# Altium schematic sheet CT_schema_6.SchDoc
size 379 x 245 mm
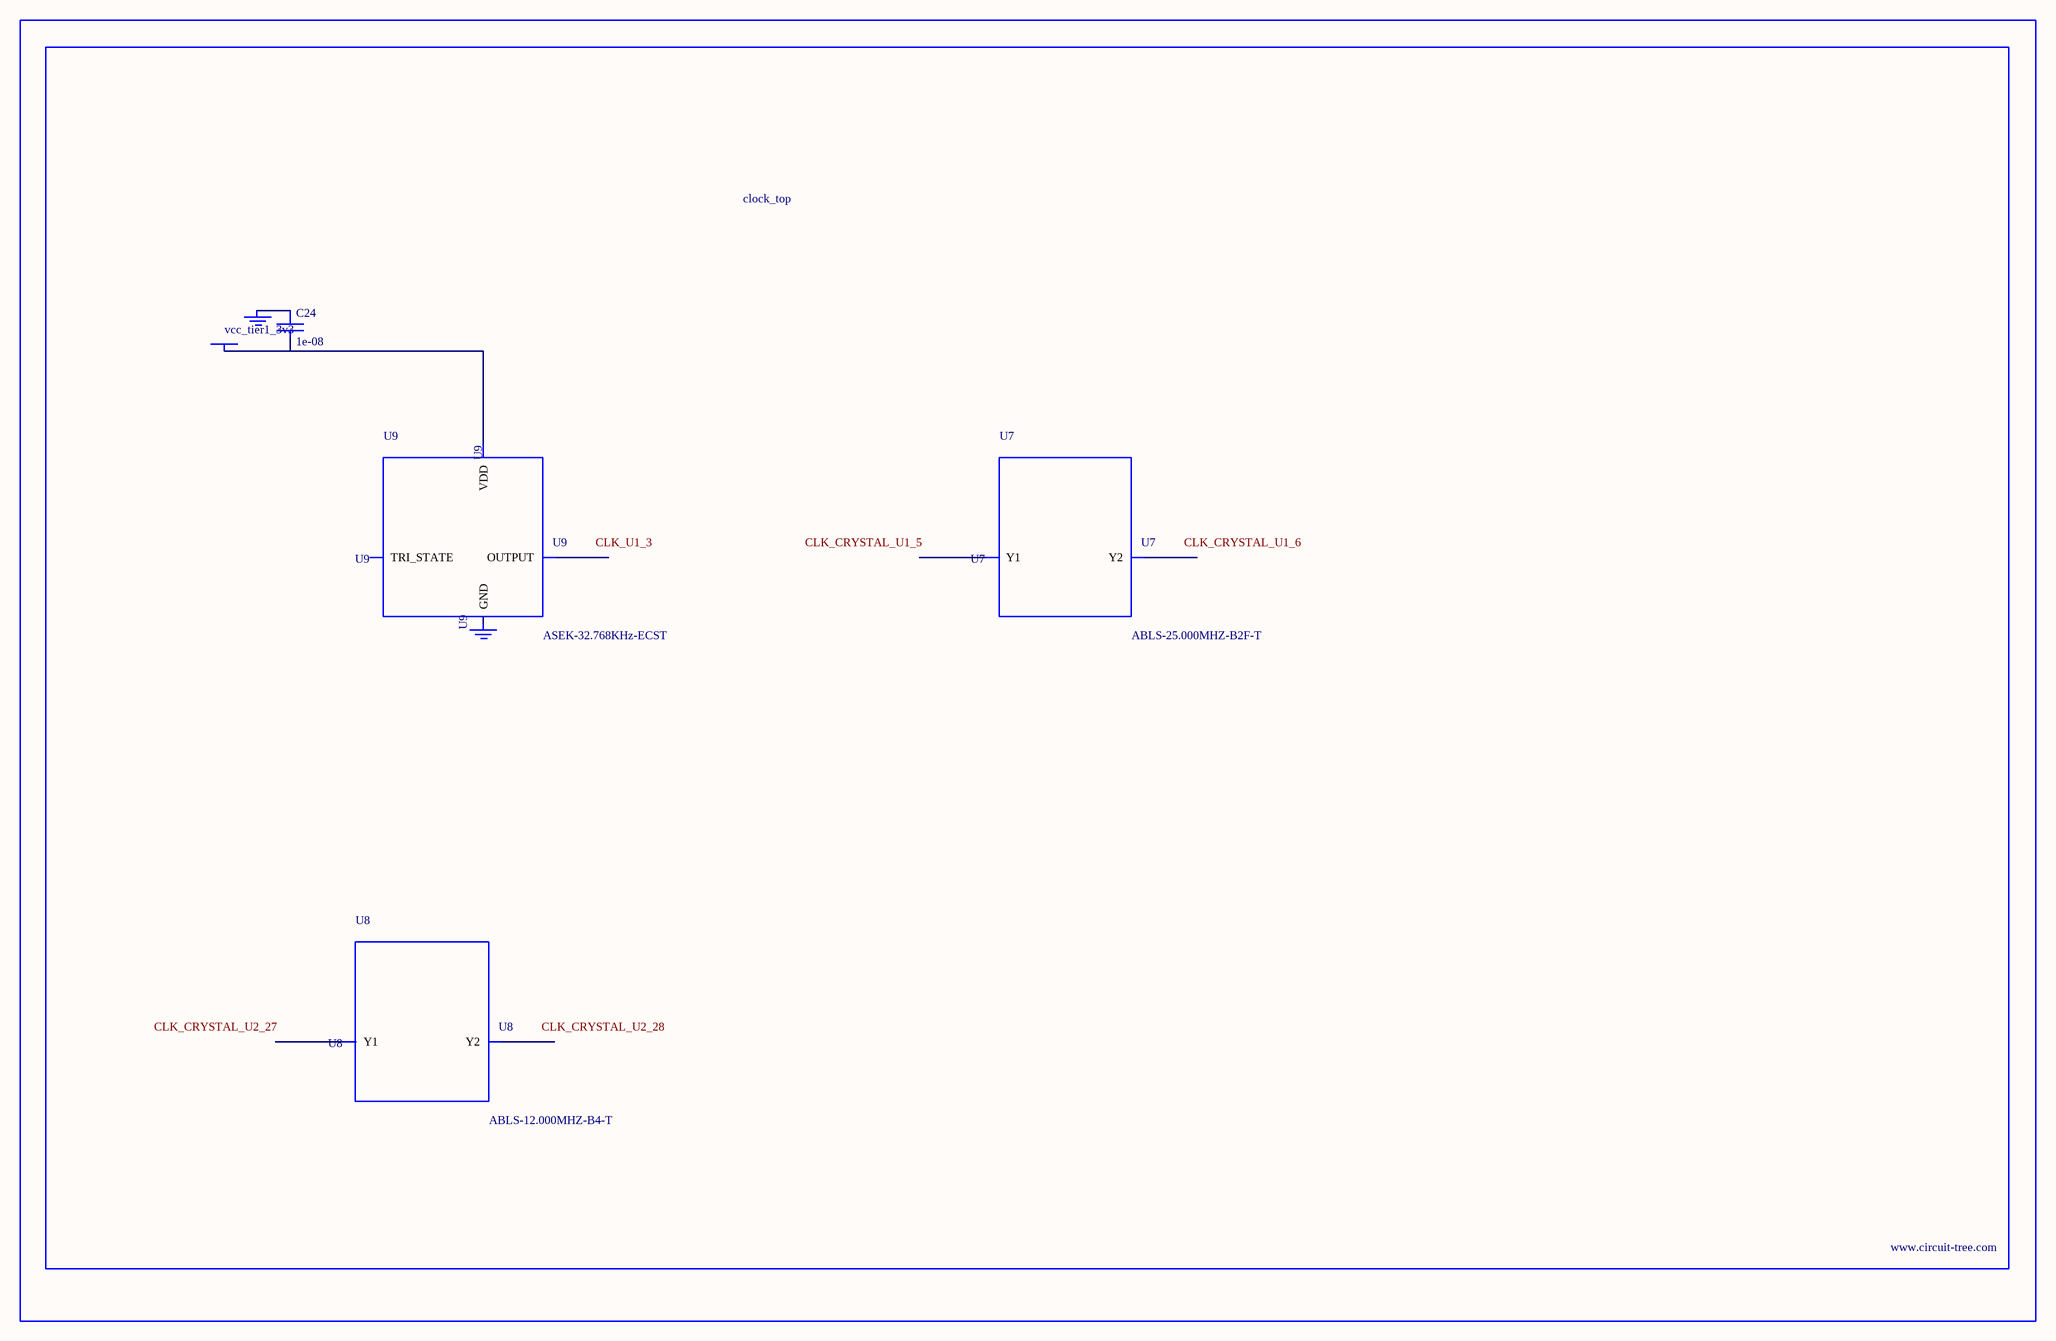
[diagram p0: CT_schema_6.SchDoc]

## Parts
BORDER5  (no value)
C24  1e-08  [C0402]
GND_INSTANCE_5_0  (no value)
GND_INSTANCE_5_1  (no value)
POWER_INSTANCE_5_0  vcc_tier1_3v3
U7  ABLS-25.000MHZ-B2F-T  [ABLS-25.000MHZ-B2F-T]
U8  ABLS-12.000MHZ-B4-T  [ABLS-12.000MHZ-B4-T]
U9  ASEK-32.768KHz-ECST  [ASEK]

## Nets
NetC24_1: C24.1 GND_INSTANCE_5_0.0(GND)
NetC24_2: C24.2 POWER_INSTANCE_5_0.0(PWR) U9.4(VDD)

Not connected (* = marked no-connect by the designer): GND_INSTANCE_5_1 0(GND); U7 1(Y1) 2(Y2); U8 1(Y1) 2(Y2); U9 1(TRI_STATE) 2(GND) 3(OUTPUT)

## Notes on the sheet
- Labels drawn without touching a wire or pin: CLK_CRYSTAL_U1_5, CLK_CRYSTAL_U1_6, CLK_CRYSTAL_U2_27, CLK_CRYSTAL_U2_28, CLK_U1_3

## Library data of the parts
BORDER5 = BORDER_PAGE5
C24 = C0402C103K3RAC
GND_INSTANCE_5_0 GND_INSTANCE_5_1 = GND
POWER_INSTANCE_5_0 = PWR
